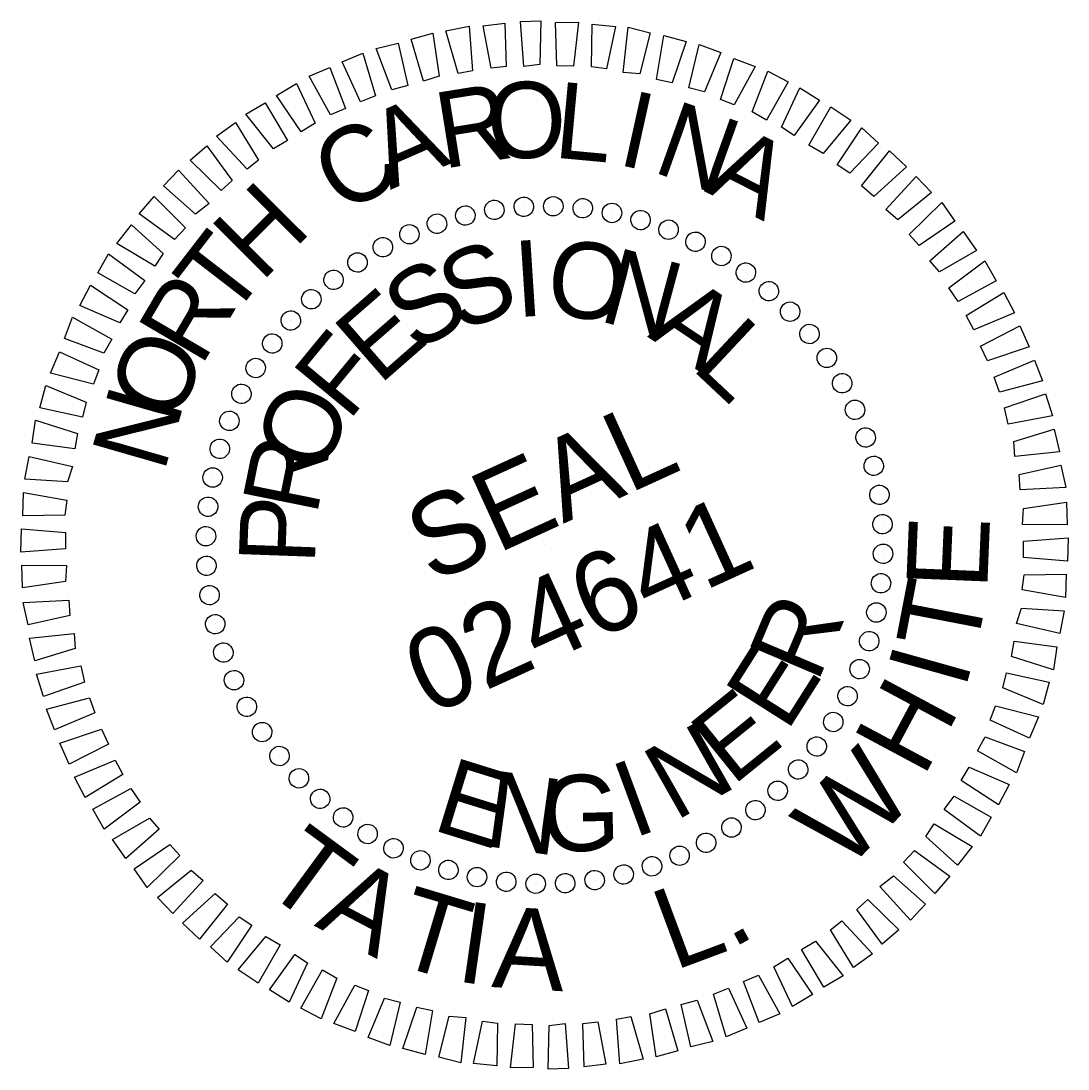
# Model space of a CAD drawing. Extents: x 2237908 to 2239894, y 658266 to 660035.
# Drawn here: x 2239665.3 to 2239742.8, y 659916.1 to 659993.7 of the extents above; entities that cross this region are included whole.
import ezdxf

# ---------------------------------------------------------------- set-up
doc = ezdxf.new("R2010")
doc.units = 0
doc.layers.add('Sheet Professional Seal CELL', color=7, linetype='Continuous')

msp = doc.modelspace()

# ---------------------------------------------------------------- linework, layer by layer
at = {"layer": 'Sheet Professional Seal CELL'}
for p, q in [((2239700.329, 659979.759), (2239700.329, 659979.759)), ((2239702.53, 659979.993), (2239702.53, 659979.993)), ((2239704.723, 659980.004), (2239704.723, 659980.004)), ((2239706.912, 659979.903), (2239706.912, 659979.903)), ((2239698.231, 659979.297), (2239698.231, 659979.297)), ((2239709.069, 659979.513), (2239709.069, 659979.513)), ((2239711.221, 659979.011), (2239711.221, 659979.011)), ((2239696.13, 659978.724), (2239696.13, 659978.724)), ((2239713.254, 659978.289), (2239713.254, 659978.289)), ((2239694.066, 659977.947), (2239694.066, 659977.947)), ((2239715.303, 659977.41), (2239715.303, 659977.41)), ((2239692.085, 659976.989), (2239692.085, 659976.989)), ((2239690.253, 659975.824), (2239690.253, 659975.824)), ((2239717.167, 659976.336), (2239717.167, 659976.336)), ((2239719.001, 659975.085), (2239719.001, 659975.085)), ((2239688.418, 659974.547), (2239688.418, 659974.547)), ((2239720.72, 659973.725), (2239720.72, 659973.725)), ((2239686.756, 659973.13), (2239686.756, 659973.13)), ((2239722.278, 659972.237), (2239722.278, 659972.237)), ((2239685.268, 659971.573), (2239685.268, 659971.573)), ((2239723.695, 659970.576), (2239723.695, 659970.576)), ((2239683.909, 659969.854), (2239683.909, 659969.854)), ((2239682.657, 659968.019), (2239682.657, 659968.019)), ((2239724.972, 659968.74), (2239724.972, 659968.74)), ((2239726.137, 659966.908), (2239726.137, 659966.908)), ((2239681.583, 659966.156), (2239681.583, 659966.156)), ((2239727.095, 659964.927), (2239727.095, 659964.927)), ((2239680.704, 659964.106), (2239680.704, 659964.106)), ((2239727.871, 659962.863), (2239727.871, 659962.863)), ((2239679.983, 659962.074), (2239679.983, 659962.074)), ((2239728.445, 659960.762), (2239728.445, 659960.762)), ((2239679.48, 659959.921), (2239679.48, 659959.921)), ((2239728.906, 659958.664), (2239728.906, 659958.664)), ((2239679.09, 659957.765), (2239679.09, 659957.765)), ((2239729.141, 659956.463), (2239729.141, 659956.463)), ((2239678.989, 659955.576), (2239678.989, 659955.576)), ((2239704.07, 659954.923), (2239704.07, 659954.923)), ((2239729.152, 659954.27), (2239729.152, 659954.27)), ((2239679, 659953.383), (2239679, 659953.383)), ((2239729.051, 659952.081), (2239729.051, 659952.081)), ((2239679.234, 659951.181), (2239679.234, 659951.181)), ((2239728.66, 659949.924), (2239728.66, 659949.924)), ((2239679.696, 659949.084), (2239679.696, 659949.084)), ((2239728.158, 659947.772), (2239728.158, 659947.772)), ((2239680.27, 659946.983), (2239680.27, 659946.983)), ((2239727.436, 659945.739), (2239727.436, 659945.739)), ((2239681.046, 659944.919), (2239681.046, 659944.919)), ((2239726.557, 659943.69), (2239726.557, 659943.69)), ((2239682.004, 659942.938), (2239682.004, 659942.938)), ((2239725.484, 659941.827), (2239725.484, 659941.827)), ((2239683.169, 659941.106), (2239683.169, 659941.106)), ((2239724.232, 659939.992), (2239724.232, 659939.992)), ((2239684.446, 659939.27), (2239684.446, 659939.27)), ((2239722.873, 659938.273), (2239722.873, 659938.273)), ((2239685.863, 659937.608), (2239685.863, 659937.608)), ((2239721.385, 659936.715), (2239721.385, 659936.715)), ((2239687.421, 659936.12), (2239687.421, 659936.12)), ((2239689.14, 659934.761), (2239689.14, 659934.761)), ((2239719.723, 659935.298), (2239719.723, 659935.298)), ((2239717.887, 659934.022), (2239717.887, 659934.022)), ((2239690.974, 659933.509), (2239690.974, 659933.509)), ((2239692.838, 659932.436), (2239692.838, 659932.436)), ((2239716.056, 659932.857), (2239716.056, 659932.857)), ((2239694.887, 659931.557), (2239694.887, 659931.557)), ((2239714.075, 659931.898), (2239714.075, 659931.898)), ((2239696.92, 659930.835), (2239696.92, 659930.835)), ((2239712.011, 659931.122), (2239712.011, 659931.122)), ((2239699.072, 659930.333), (2239699.072, 659930.333)), ((2239707.812, 659930.087), (2239707.812, 659930.087)), ((2239709.909, 659930.548), (2239709.909, 659930.548)), ((2239701.228, 659929.942), (2239701.228, 659929.942)), ((2239703.417, 659929.841), (2239703.417, 659929.841)), ((2239705.611, 659929.852), (2239705.611, 659929.852))]:
    msp.add_line(p, q, dxfattribs=at)
for points in [[(2239702.543, 659990.33), (2239702.282, 659993.673), (2239703.805, 659993.708), (2239703.734, 659990.489)], [(2239704.984, 659990.399), (2239704.897, 659993.602), (2239706.598, 659993.608), (2239706.213, 659990.355)], [(2239695.12, 659989.254), (2239694.202, 659992.352), (2239695.807, 659992.809), (2239696.274, 659989.615)], [(2239697.669, 659989.811), (2239696.775, 659992.976), (2239698.488, 659993.317), (2239698.728, 659990.019)], [(2239700.122, 659990.216), (2239699.518, 659993.347), (2239701.136, 659993.535), (2239701.223, 659990.333)], [(2239707.554, 659990.307), (2239707.6, 659993.46), (2239709.317, 659993.309), (2239708.667, 659990.155)], [(2239709.888, 659989.888), (2239710.277, 659993.253), (2239711.896, 659992.837), (2239711.138, 659989.798)], [(2239692.771, 659988.622), (2239691.604, 659991.662), (2239693.23, 659992.074), (2239693.945, 659988.938)], [(2239712.376, 659989.374), (2239712.918, 659992.643), (2239714.557, 659992.182), (2239713.53, 659989.131)], [(2239690.434, 659987.721), (2239689.085, 659990.678), (2239690.607, 659991.317), (2239691.546, 659988.174)], [(2239714.748, 659988.752), (2239715.534, 659991.968), (2239717.124, 659991.374), (2239715.923, 659988.463)], [(2239717.111, 659987.906), (2239718.093, 659990.936), (2239719.682, 659990.342), (2239718.126, 659987.489)], [(2239688.229, 659986.771), (2239686.653, 659989.624), (2239688.175, 659990.263), (2239689.342, 659987.223)], [(2239719.45, 659986.994), (2239720.61, 659989.996), (2239722.125, 659989.203), (2239720.502, 659986.375)], [(2239686.058, 659985.506), (2239684.23, 659988.19), (2239685.694, 659989.077), (2239687.088, 659986.141)], [(2239721.624, 659985.842), (2239722.982, 659988.77), (2239724.448, 659987.844), (2239722.564, 659985.227)], [(2239683.999, 659984.238), (2239681.944, 659986.817), (2239683.383, 659987.638), (2239685.029, 659984.872)], [(2239723.658, 659984.517), (2239725.28, 659987.345), (2239726.767, 659986.374), (2239724.709, 659983.897)], [(2239682.044, 659982.741), (2239679.781, 659985.172), (2239681.183, 659986.196), (2239682.895, 659983.404)], [(2239725.753, 659983.054), (2239727.575, 659985.808), (2239728.809, 659984.668), (2239726.693, 659982.439)], [(2239680.13, 659981.154), (2239677.839, 659983.407), (2239679.062, 659984.459), (2239680.94, 659981.908)], [(2239727.555, 659981.513), (2239729.617, 659984.102), (2239730.872, 659982.915), (2239728.466, 659980.719)], [(2239678.232, 659979.41), (2239675.846, 659981.509), (2239676.962, 659982.677), (2239679.245, 659980.201)], [(2239729.349, 659979.748), (2239731.585, 659982.196), (2239732.728, 659981.014), (2239730.24, 659979)], [(2239676.666, 659977.542), (2239674.049, 659979.426), (2239675.169, 659980.706), (2239677.48, 659978.408)], [(2239731.073, 659977.896), (2239733.507, 659980.27), (2239734.465, 659978.893), (2239731.827, 659977.086)], [(2239675.208, 659975.558), (2239672.404, 659977.247), (2239673.483, 659978.618), (2239675.823, 659976.498)], [(2239732.614, 659975.961), (2239735.086, 659978.133), (2239736.064, 659976.71), (2239733.323, 659975.131)], [(2239673.725, 659973.508), (2239670.983, 659975.06), (2239671.772, 659976.464), (2239674.477, 659974.51)], [(2239734.019, 659973.964), (2239736.686, 659975.95), (2239737.528, 659974.465), (2239734.699, 659972.956)], [(2239672.618, 659971.355), (2239669.666, 659972.646), (2239670.459, 659974.162), (2239673.213, 659972.34)], [(2239735.288, 659971.905), (2239738.079, 659973.618), (2239738.876, 659972.112), (2239735.877, 659970.855)], [(2239671.442, 659969.115), (2239668.527, 659970.204), (2239669.121, 659971.793), (2239672.016, 659970.146)], [(2239736.371, 659969.651), (2239739.266, 659971.136), (2239739.971, 659969.589), (2239736.869, 659968.559)], [(2239670.666, 659966.838), (2239667.496, 659967.645), (2239668.156, 659969.21), (2239671.062, 659967.898)], [(2239737.363, 659967.356), (2239740.361, 659968.613), (2239740.955, 659967.071), (2239737.769, 659966.223)], [(2239669.862, 659964.383), (2239666.688, 659965.078), (2239667.149, 659966.718), (2239670.126, 659965.492)], [(2239738.131, 659965.068), (2239741.167, 659966.123), (2239741.69, 659964.493), (2239738.401, 659963.873)], [(2239669.286, 659962.032), (2239666.124, 659962.458), (2239666.387, 659964.172), (2239669.483, 659963.166)], [(2239738.825, 659962.582), (2239741.811, 659963.505), (2239742.198, 659961.813), (2239738.897, 659961.461)], [(2239668.751, 659959.59), (2239665.581, 659959.793), (2239665.91, 659961.482), (2239669.105, 659960.741)], [(2239739.229, 659960.129), (2239742.319, 659960.824), (2239742.686, 659959.177), (2239739.301, 659959.008)], [(2239668.551, 659957.136), (2239665.439, 659957.091), (2239665.479, 659958.812), (2239668.703, 659958.249)], [(2239739.542, 659957.634), (2239742.736, 659958.101), (2239742.788, 659956.421), (2239739.478, 659956.451)], [(2239668.595, 659954.628), (2239665.298, 659954.388), (2239665.337, 659956.11), (2239668.594, 659955.836)], [(2239739.545, 659955.218), (2239742.843, 659955.457), (2239742.804, 659953.736), (2239739.547, 659954.009)], [(2239668.598, 659952.211), (2239665.404, 659951.744), (2239665.353, 659953.424), (2239668.663, 659953.395)], [(2239739.59, 659952.71), (2239742.701, 659952.755), (2239742.662, 659951.034), (2239739.438, 659951.597)], [(2239668.912, 659949.717), (2239665.821, 659949.022), (2239665.455, 659950.668), (2239668.84, 659950.838)], [(2239739.39, 659950.256), (2239742.56, 659950.053), (2239742.231, 659948.364), (2239739.035, 659949.105)], [(2239669.316, 659947.263), (2239666.329, 659946.341), (2239665.942, 659948.033), (2239669.244, 659948.385)], [(2239738.855, 659947.814), (2239742.017, 659947.387), (2239741.754, 659945.674), (2239738.658, 659946.68)], [(2239670.01, 659944.777), (2239666.974, 659943.722), (2239666.45, 659945.352), (2239669.739, 659945.973)], [(2239738.278, 659945.463), (2239741.453, 659944.767), (2239740.992, 659943.128), (2239738.015, 659944.353)], [(2239670.778, 659942.49), (2239667.78, 659941.232), (2239667.186, 659942.775), (2239670.371, 659943.623)], [(2239737.474, 659943.008), (2239740.645, 659942.201), (2239739.985, 659940.636), (2239737.078, 659941.948)], [(2239671.77, 659940.194), (2239668.875, 659938.709), (2239668.17, 659940.256), (2239671.272, 659941.286)], [(2239736.699, 659940.731), (2239739.614, 659939.642), (2239739.02, 659938.052), (2239736.125, 659939.7)], [(2239672.853, 659937.94), (2239670.061, 659936.228), (2239669.265, 659937.733), (2239672.264, 659938.991)], [(2239735.522, 659938.491), (2239738.474, 659937.199), (2239737.682, 659935.684), (2239734.928, 659937.505)], [(2239674.121, 659935.881), (2239671.455, 659933.896), (2239670.613, 659935.38), (2239673.441, 659936.89)], [(2239734.416, 659936.338), (2239737.157, 659934.785), (2239736.369, 659933.381), (2239733.664, 659935.336)], [(2239675.526, 659933.884), (2239673.054, 659931.713), (2239672.076, 659933.135), (2239674.818, 659934.715)], [(2239732.933, 659934.288), (2239735.736, 659932.599), (2239734.658, 659931.228), (2239732.317, 659933.348)], [(2239677.068, 659931.949), (2239674.634, 659929.575), (2239673.676, 659930.952), (2239676.314, 659932.76)], [(2239731.475, 659932.304), (2239734.092, 659930.42), (2239732.972, 659929.14), (2239730.66, 659931.438)], [(2239678.792, 659930.098), (2239676.556, 659927.649), (2239675.412, 659928.831), (2239677.901, 659930.845)], [(2239729.908, 659930.436), (2239732.294, 659928.336), (2239731.179, 659927.168), (2239728.896, 659929.644)], [(2239680.586, 659928.333), (2239678.524, 659925.744), (2239677.269, 659926.93), (2239679.674, 659929.126)], [(2239728.011, 659928.691), (2239730.302, 659926.439), (2239729.079, 659925.386), (2239727.201, 659927.937)], [(2239682.387, 659926.791), (2239680.566, 659924.037), (2239679.331, 659925.178), (2239681.447, 659927.407)], [(2239726.097, 659927.104), (2239728.359, 659924.674), (2239726.958, 659923.65), (2239725.246, 659926.441)], [(2239684.483, 659925.329), (2239682.86, 659922.501), (2239681.373, 659923.472), (2239683.431, 659925.949)], [(2239724.142, 659925.608), (2239726.197, 659923.028), (2239724.758, 659922.207), (2239723.112, 659924.974)], [(2239686.516, 659924.003), (2239685.159, 659921.076), (2239683.693, 659922.001), (2239685.576, 659924.619)], [(2239722.082, 659924.339), (2239723.91, 659921.656), (2239722.447, 659920.769), (2239721.053, 659923.705)], [(2239688.69, 659922.851), (2239687.531, 659919.85), (2239686.016, 659920.643), (2239687.638, 659923.471)], [(2239719.911, 659923.075), (2239721.487, 659920.221), (2239719.965, 659919.582), (2239718.799, 659922.622)], [(2239691.029, 659921.94), (2239690.048, 659918.909), (2239688.458, 659919.503), (2239690.015, 659922.356)], [(2239717.707, 659922.124), (2239719.055, 659919.167), (2239717.533, 659918.528), (2239716.594, 659921.672)], [(2239693.393, 659921.094), (2239692.607, 659917.878), (2239691.017, 659918.472), (2239692.218, 659921.382)], [(2239695.765, 659920.472), (2239695.223, 659917.202), (2239693.583, 659917.664), (2239694.61, 659920.715)], [(2239715.37, 659921.224), (2239716.537, 659918.184), (2239714.911, 659917.772), (2239714.195, 659920.908)], [(2239698.253, 659919.958), (2239697.863, 659916.593), (2239696.245, 659917.009), (2239697.003, 659920.047)], [(2239710.472, 659920.034), (2239711.366, 659916.87), (2239709.653, 659916.529), (2239709.413, 659919.826)], [(2239713.02, 659920.592), (2239713.939, 659917.494), (2239712.334, 659917.037), (2239711.866, 659920.231)], [(2239700.587, 659919.538), (2239700.541, 659916.385), (2239698.824, 659916.536), (2239699.474, 659919.69)], [(2239703.157, 659919.446), (2239703.243, 659916.244), (2239701.543, 659916.237), (2239701.928, 659919.49)], [(2239705.598, 659919.515), (2239705.859, 659916.172), (2239704.336, 659916.137), (2239704.407, 659919.357)], [(2239708.019, 659919.63), (2239708.622, 659916.498), (2239707.005, 659916.31), (2239706.918, 659919.513)]]:
    msp.add_lwpolyline(points, close=True, dxfattribs=at)
for centre, major_axis in [((2239700.358, 659979.727), (-0.107, 0.712)), ((2239702.534, 659979.956), (-0.044, 0.719)), ((2239704.721, 659979.994), (0.019, 0.72)), ((2239706.904, 659979.842), (0.081, 0.715)), ((2239698.21, 659979.309), (-0.168, 0.7)), ((2239709.065, 659979.5), (0.143, 0.706)), ((2239711.188, 659978.972), (0.204, 0.69)), ((2239696.107, 659978.705), (-0.229, 0.683)), ((2239713.257, 659978.26), (0.264, 0.67)), ((2239694.065, 659977.921), (-0.287, 0.66)), ((2239715.256, 659977.37), (0.321, 0.644)), ((2239692.098, 659976.961), (-0.344, 0.633)), ((2239690.223, 659975.834), (-0.398, 0.6)), ((2239717.17, 659976.31), (0.376, 0.614)), ((2239718.984, 659975.087), (0.428, 0.579)), ((2239688.453, 659974.547), (-0.448, 0.563)), ((2239720.685, 659973.71), (0.477, 0.539)), ((2239686.803, 659973.111), (-0.496, 0.522)), ((2239722.259, 659972.191), (0.522, 0.496)), ((2239685.283, 659971.537), (-0.539, 0.477)), ((2239723.695, 659970.54), (0.563, 0.448)), ((2239683.906, 659969.837), (-0.579, 0.428)), ((2239724.981, 659968.77), (0.6, 0.398)), ((2239682.683, 659968.022), (-0.614, 0.376)), ((2239726.109, 659966.895), (0.633, 0.344)), ((2239681.623, 659966.109), (-0.644, 0.321)), ((2239727.068, 659964.928), (0.66, 0.287)), ((2239680.734, 659964.11), (-0.67, 0.264)), ((2239727.853, 659962.886), (0.683, 0.229)), ((2239680.022, 659962.041), (-0.69, 0.204)), ((2239728.456, 659960.783), (0.7, 0.168)), ((2239679.493, 659959.918), (-0.706, 0.143)), ((2239728.874, 659958.635), (0.712, 0.107)), ((2239679.151, 659957.757), (-0.715, 0.081)), ((2239729.103, 659956.459), (0.719, 0.044)), ((2239678.999, 659955.574), (-0.72, 0.019)), ((2239729.142, 659954.272), (0.72, -0.019)), ((2239679.037, 659953.386), (-0.719, -0.044)), ((2239728.99, 659952.089), (0.715, -0.081)), ((2239679.267, 659951.21), (-0.712, -0.107)), ((2239728.648, 659949.928), (0.706, -0.143)), ((2239679.685, 659949.063), (-0.7, -0.168)), ((2239728.119, 659947.805), (0.69, -0.204)), ((2239680.288, 659946.96), (-0.683, -0.229)), ((2239727.407, 659945.736), (0.67, -0.264)), ((2239681.073, 659944.917), (-0.66, -0.287)), ((2239726.518, 659943.737), (0.644, -0.321)), ((2239682.032, 659942.951), (-0.633, -0.344)), ((2239725.457, 659941.823), (0.614, -0.376)), ((2239683.159, 659941.076), (-0.6, -0.398)), ((2239724.234, 659940.009), (0.579, -0.428)), ((2239684.446, 659939.306), (-0.563, -0.448)), ((2239722.858, 659938.308), (0.539, -0.477)), ((2239685.882, 659937.655), (-0.522, -0.496)), ((2239721.338, 659936.734), (0.496, -0.522)), ((2239687.456, 659936.135), (-0.477, -0.539)), ((2239689.157, 659934.759), (-0.428, -0.579)), ((2239719.687, 659935.298), (0.448, -0.563)), ((2239717.917, 659934.012), (0.398, -0.6)), ((2239690.971, 659933.536), (-0.376, -0.614)), ((2239692.885, 659932.475), (-0.321, -0.644)), ((2239716.042, 659932.885), (0.344, -0.633)), ((2239694.883, 659931.586), (-0.264, -0.67)), ((2239714.076, 659931.925), (0.287, -0.66)), ((2239696.952, 659930.874), (-0.204, -0.69)), ((2239712.033, 659931.141), (0.229, -0.683)), ((2239699.075, 659930.345), (-0.143, -0.706)), ((2239701.237, 659930.003), (-0.081, -0.715)), ((2239707.783, 659930.119), (0.107, -0.712)), ((2239709.93, 659930.537), (0.168, -0.7)), ((2239703.419, 659929.851), (-0.019, -0.72)), ((2239705.607, 659929.89), (0.044, -0.719))]:
    msp.add_ellipse(centre, major_axis=major_axis, ratio=0.999708, dxfattribs=at)

# ---------------------------------------------------------------- texts
for s, height, rotation, p in [('R', 5.638, 9.13336, (2239696.543, 659982.759)), ('O', 5.638, 1.93343, (2239699.902, 659983.466)), ('L', 5.638, 354.73314, (2239704.673, 659983.608)), ('I', 5.638, 347.5324, (2239709.354, 659983.105)), ('A', 5.638, 23.53258, (2239692.639, 659981.198)), ('N', 5.639, 340.33117, (2239711.953, 659982.587)), ('C', 5.638, 30.73213, (2239689.169, 659979.286)), ('A', 5.639, 333.12941, (2239715.861, 659981.126)), ('H', 5.638, 45.13174, (2239683.084, 659974.313)), ('T', 5.638, 52.33203, (2239680.811, 659971.464)), ('I', 5.638, 3.70186, (2239701.99, 659971.779)), ('O', 5.638, 354.34574, (2239704.1, 659971.972)), ('S', 5.638, 22.41266, (2239697.787, 659970.632)), ('N', 5.638, 344.98887, (2239707.978, 659971.542)), ('S', 5.638, 31.76787, (2239694.532, 659969.092)), ('R', 5.638, 59.53277, (2239678.631, 659968.051)), ('E', 5.638, 41.12333, (2239691.828, 659966.706)), ('A', 5.639, 326.27253, (2239711.649, 659970.358)), ('L', 5.639, 316.91311, (2239714.855, 659968.028)), ('O', 5.638, 66.734, (2239676.778, 659963.799)), ('F', 5.638, 50.47929, (2239689.539, 659964.013)), ('O', 5.639, 69.1935, (2239687.76, 659959.96)), ('N', 5.639, 73.93576, (2239675.888, 659960.207)), ('SEAL', 5.9982, 24.51226, (2239695.712, 659952.044)), ('R', 5.639, 78.55191, (2239687.185, 659957.005)), ('P', 5.639, 87.91115, (2239687.057, 659953.429)), ('024641', 5.9982, 24.51226, (2239695.591, 659942.255)), ('E', 5.998, 87.63115, (2239736.85, 659951.565)), ('T', 5.998, 79.10933, (2239735.991, 659946.745)), ('R', 5.639, 66.99367, (2239724.264, 659944.622)), ('E', 5.638, 57.63635, (2239722.009, 659941.011)), ('I', 5.998, 74.34486, (2239735.201, 659944.122)), ('H', 5.998, 61.83328, (2239732.122, 659937.634)), ('E', 5.638, 38.92402, (2239717.995, 659937.038)), ('N', 5.638, 29.56865, (2239713.741, 659934.439)), ('W', 5.998, 46.12601, (2239726.394, 659930.686)), ('E', 5.638, 342.78915, (2239695.641, 659933.879)), ('I', 5.638, 20.21346, (2239710.63, 659933.185)), ('N', 5.638, 352.14622, (2239699.491, 659932.667)), ('G', 5.638, 1.5025, (2239703.882, 659932.197)), ('T', 5.998, 323.6774, (2239682.977, 659929.608)), ('A', 5.998, 332.19922, (2239686.961, 659926.761)), ('T', 5.998, 343.27759, (2239692.691, 659923.999)), ('L', 5.998, 20.42498, (2239713.674, 659923.402)), ('I', 5.998, 351.79941, (2239697.399, 659922.654)), ('A', 5.998, 356.56388, (2239700.103, 659922.211)), ('.', 5.998, 28.28829, (2239717.896, 659925.012))]:
    msp.add_text(s, height=height, rotation=rotation, dxfattribs=at).set_placement(p)

doc.saveas('drawing.dxf')
